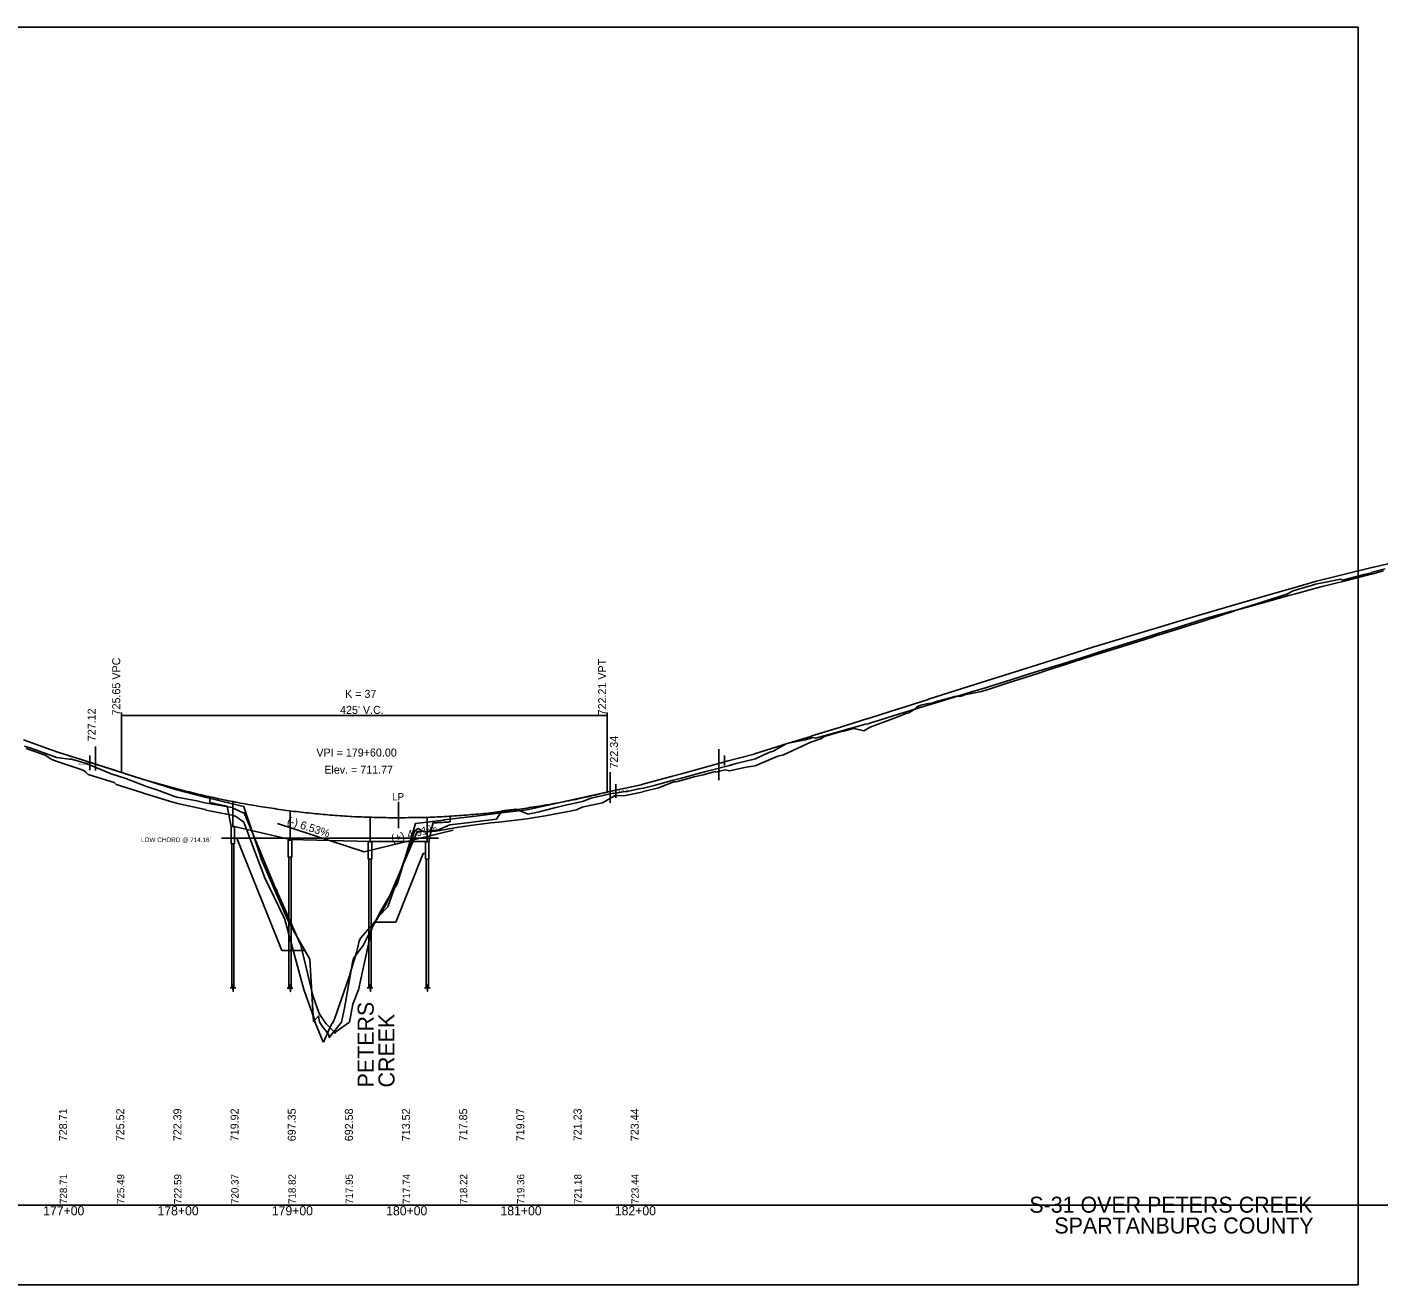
# Model space of a CAD drawing. Extents: x 1741783 to 1745041, y 1152835 to 1153935.
# Drawn here: x 1743218 to 1744400, y 1152835 to 1153935 of the extents above; entities that cross this region are included whole.
import ezdxf

# ---------------------------------------------------------------- set-up
doc = ezdxf.new("R2010")
doc.units = 0
for name, color, linetype in [('BR_CONCRETE', 7, 'Continuous'), ('BR_EXIST_GROUND_LT', 7, 'Continuous'), ('BR_EXIST_GROUND_RT', 7, 'Continuous'), ('BR_USER NOTES', 7, 'Continuous'), ('GN_Clip', 7, 'Continuous'), ('RD_DDB_GradeTX', 7, 'Continuous'), ('RD_DDB_Profile_EX', 7, 'Continuous'), ('RD_DDB_Profile_Lbl', 7, 'Continuous'), ('RD_DDB_Profile_PR', 7, 'Continuous'), ('RD_DDB_StaTX', 7, 'Continuous'), ('RD_DDB_StripGrade', 7, 'Continuous'), ('RD_DDB_VCLbl', 7, 'Continuous'), ('RD_GPK_Profile_Cell', 7, 'Continuous'), ('RD_SHT_TX', 7, 'Continuous')]:
    doc.layers.add(name, color=color, linetype=linetype)

msp = doc.modelspace()

# ---------------------------------------------------------------- linework, layer by layer
at = {"layer": 'BR_CONCRETE'}
for p, q in [((1743377.7, 1153257.2), (1743377.7, 1153262.3)), ((1743396.2, 1153236.2), (1743392.7, 1153254)), ((1743397.7, 1153236.6), (1743397.7, 1153258.1)), ((1743447.7, 1153224.9), (1743447.7, 1153250)), ((1743517.7, 1153223), (1743517.7, 1153244.3)), ((1743567.7, 1153223.2), (1743567.7, 1153244.4)), ((1743587.7, 1153240.3), (1743587.7, 1153245.3)), ((1743397.7, 1153236.6), (1743397.7, 1153236.2)), ((1743397.7, 1153236.6), (1743447.7, 1153224.9)), ((1743569.2, 1153222.8), (1743572.6, 1153239.5)), ((1743396.7, 1153095.1), (1743396.7, 1153221.2)), ((1743398.7, 1153095.1), (1743398.7, 1153221.2)), ((1743399.2, 1153226), (1743401.2, 1153226)), ((1743401.2, 1153226), (1743440.5, 1153127.8)), ((1743447.7, 1153224.9), (1743447.7, 1153224.4)), ((1743517.7, 1153223.2), (1743447.7, 1153224.9)), ((1743517.7, 1153223.2), (1743517.7, 1153222.8)), ((1743517.7, 1153223.2), (1743567.7, 1153223.2)), ((1743567.7, 1153223.2), (1743567.7, 1153222.8)), ((1743446.7, 1153094.9), (1743446.7, 1153209.4)), ((1743446.7, 1153209.4), (1743448.7, 1153209.4)), ((1743448.7, 1153094.9), (1743448.7, 1153209.4)), ((1743516.7, 1153095.1), (1743516.7, 1153207.8)), ((1743516.7, 1153207.8), (1743518.7, 1153207.8)), ((1743518.7, 1153095.1), (1743518.7, 1153207.8)), ((1743564.2, 1153212.8), (1743540.2, 1153152.8)), ((1743566.2, 1153212.8), (1743564.2, 1153212.8)), ((1743566.7, 1153095.1), (1743566.7, 1153207.8)), ((1743568.7, 1153095.1), (1743568.7, 1153207.8)), ((1743522.2, 1153152.8), (1743540.2, 1153152.8)), ((1743440.5, 1153127.8), (1743460.8, 1153127.8))]:
    msp.add_line(p, q, dxfattribs=at)
for points in [[(1743396.2, 1153236.2), (1743399.2, 1153236.2), (1743399.2, 1153221.2), (1743396.2, 1153221.2)], [(1743446.2, 1153224.4), (1743449.2, 1153224.4), (1743449.2, 1153209.4), (1743446.2, 1153209.4)], [(1743516.2, 1153222.8), (1743519.2, 1153222.8), (1743519.2, 1153207.8), (1743516.2, 1153207.8)], [(1743569.2, 1153222.8), (1743566.2, 1153222.8), (1743566.2, 1153207.8), (1743569.2, 1153207.8)]]:
    msp.add_lwpolyline(points, close=True, dxfattribs=at)
for points in [[(1743400.2, 1153095.1), (1743398, 1153095.1), (1743398, 1153092.1), (1743397.4, 1153098.1), (1743397.4, 1153095.1), (1743395.3, 1153095.1)], [(1743450.2, 1153094.9), (1743448, 1153094.9), (1743448, 1153091.9), (1743447.4, 1153097.9), (1743447.4, 1153094.9), (1743445.3, 1153094.9)], [(1743520.2, 1153095.1), (1743518, 1153095.1), (1743518, 1153092.1), (1743517.4, 1153098.1), (1743517.4, 1153095.1), (1743515.3, 1153095.1)], [(1743570.2, 1153095.1), (1743568, 1153095.1), (1743568, 1153092.1), (1743567.4, 1153098.1), (1743567.4, 1153095.1), (1743565.3, 1153095.1)]]:
    msp.add_lwpolyline(points, dxfattribs=at)
for points in [[(1743377.7, 1153257.2), (1743379.7, 1153256.7), (1743381.7, 1153256.3), (1743384.8, 1153255.6), (1743385.9, 1153255.4), (1743388.1, 1153254.9), (1743389.2, 1153254.7), (1743391.1, 1153254.3), (1743391.9, 1153254.2), (1743392.7, 1153254)], [(1743572.6, 1153239.5), (1743574.7, 1153239.6), (1743576.9, 1153239.7), (1743581.3, 1153239.9), (1743583.6, 1153240.1), (1743586.5, 1153240.2), (1743587.1, 1153240.3), (1743587.7, 1153240.3)]]:
    msp.add_open_spline(points, degree=3, dxfattribs=at)
at = {"layer": 'BR_EXIST_GROUND_LT'}
msp.add_lwpolyline([(1743215.6, 1153306.5), (1743220.9, 1153304.7), (1743240.5, 1153297.7), (1743241.2, 1153297.5), (1743243.5, 1153296.7), (1743254.7, 1153295.2), (1743256.5, 1153295.1), (1743269.7, 1153291.3), (1743291.4, 1153282.3), (1743297.8, 1153280.3), (1743304.2, 1153278.2), (1743322.1, 1153271.3), (1743331.2, 1153268.5), (1743346.2, 1153262.8), (1743348.7, 1153262), (1743366.1, 1153258.7), (1743373.2, 1153256.9), (1743397, 1153252.8), (1743397.5, 1153252.5), (1743406.8, 1153248.4), (1743407.7, 1153248.2), (1743435.3, 1153181.6), (1743435.5, 1153181.9), (1743436.5, 1153179.3), (1743457.2, 1153132.5), (1743467.8, 1153088.6), (1743473.2, 1153072.7), (1743477.8, 1153065.7), (1743479.4, 1153063.9), (1743486.9, 1153056.1), (1743487, 1153055.5), (1743488.2, 1153057), (1743499.7, 1153065.3), (1743502.7, 1153081), (1743507.7, 1153093.4), (1743520, 1153149.4), (1743523.3, 1153155), (1743525, 1153157.7), (1743533.3, 1153166.1), (1743555.7, 1153229.5), (1743556.7, 1153231.3), (1743557.6, 1153233.1), (1743559.7, 1153234.7), (1743565, 1153231.6), (1743576.6, 1153233), (1743587.5, 1153237.7), (1743602.7, 1153239.4), (1743611.8, 1153240.8), (1743628.2, 1153242.7), (1743633, 1153250), (1743645.2, 1153251.4), (1743656.1, 1153247.2), (1743665.5, 1153249.1), (1743679.1, 1153252.6), (1743680.5, 1153252.9), (1743688.7, 1153255), (1743703.5, 1153258.3), (1743711.1, 1153261.1), (1743730.5, 1153265.5), (1743731, 1153265.3), (1743739.2, 1153266.5), (1743742.7, 1153266.9), (1743752.8, 1153269.4), (1743757, 1153269.8), (1743766.2, 1153272.3), (1743782, 1153276.5), (1743789.1, 1153278.4), (1743807.1, 1153283.2), (1743811.5, 1153284.4), (1743832.1, 1153289.8), (1743833, 1153290), (1743838, 1153291.3), (1743854.9, 1153295.5), (1743856.6, 1153296.4), (1743861.7, 1153298.7), (1743867.4, 1153301.2), (1743870.2, 1153302.1), (1743881.6, 1153308.7), (1743882.1, 1153308.8), (1743898.5, 1153312.1), (1743903.2, 1153313.6), (1743904.9, 1153314.1), (1743907.5, 1153313.6), (1743927.4, 1153319.1), (1743931.2, 1153320.3), (1743951, 1153325.7), (1743953.5, 1153326.2), (1743954.8, 1153326.7), (1743955.8, 1153326.9), (1743957.9, 1153327.5), (1743980.8, 1153334.7), (1743985.7, 1153336.2), (1744005.7, 1153342.4), (1744012.7, 1153344.5), (1744030.7, 1153350), (1744043.9, 1153354.1), (1744053.1, 1153356.8), (1744068.8, 1153361.7), (1744078.1, 1153364.6), (1744094.6, 1153369.7), (1744103, 1153372.4), (1744120.5, 1153377.8), (1744128, 1153380.1), (1744145.6, 1153385.6), (1744151.7, 1153387.5), (1744157.8, 1153389.5), (1744176.6, 1153395.4), (1744182.3, 1153397.3), (1744201.6, 1153403.4), (1744206.7, 1153405.1), (1744226.5, 1153411.3), (1744230.1, 1153412.5), (1744246.6, 1153417.7), (1744251.3, 1153419), (1744271.5, 1153424.6), (1744276.6, 1153425.9), (1744296.5, 1153431.4), (1744301.9, 1153432.8), (1744321.4, 1153438.3), (1744327.3, 1153439.8), (1744345, 1153444.7), (1744350.6, 1153446.2), (1744369.9, 1153451), (1744377.7, 1153453), (1744394.9, 1153457.3), (1744404.3, 1153459.8)], dxfattribs=at)
at = {"layer": 'BR_EXIST_GROUND_RT'}
msp.add_lwpolyline([(1743216.9, 1153304.6), (1743233.6, 1153298.6), (1743239.5, 1153294.9), (1743244, 1153293.3), (1743265.8, 1153286), (1743267.6, 1153285.1), (1743269, 1153283.9), (1743271.2, 1153281.9), (1743293.9, 1153274.7), (1743295.7, 1153273.1), (1743318.9, 1153265.9), (1743319.5, 1153265.6), (1743343.2, 1153258.3), (1743344.3, 1153257.8), (1743349.3, 1153256.3), (1743373.5, 1153251.3), (1743374.2, 1153250.7), (1743398.7, 1153245.8), (1743399.1, 1153245.5), (1743399.9, 1153245.4), (1743407.3, 1153240), (1743418.8, 1153209.7), (1743424.7, 1153193.7), (1743425.3, 1153191.9), (1743441.9, 1153157.5), (1743443.2, 1153155.1), (1743459.9, 1153093.8), (1743468.8, 1153068.5), (1743469.3, 1153065.4), (1743476.5, 1153048.6), (1743477, 1153047.8), (1743483.8, 1153062.9), (1743485.5, 1153065.2), (1743487, 1153068.8), (1743499.6, 1153105.8), (1743500.4, 1153108), (1743505.9, 1153126), (1743506.6, 1153129.5), (1743508.1, 1153136.1), (1743509.3, 1153138.6), (1743523.6, 1153155.1), (1743531.7, 1153168.5), (1743558.5, 1153231.2), (1743559.2, 1153231.9), (1743560.5, 1153232.1), (1743569.1, 1153231.7), (1743577.1, 1153232.6), (1743595.3, 1153235.8), (1743601.4, 1153236.5), (1743605.3, 1153237.2), (1743623.5, 1153239.4), (1743630.5, 1153240.1), (1743647.5, 1153242.2), (1743655, 1153243), (1743672.5, 1153245.9), (1743679.9, 1153247.5), (1743691.3, 1153249.4), (1743698.4, 1153250.9), (1743703.4, 1153253.3), (1743720.9, 1153257), (1743731.6, 1153263), (1743741.2, 1153263.4), (1743755.4, 1153266.4), (1743755.8, 1153266.5), (1743770.1, 1153270.1), (1743783.5, 1153275.4), (1743784.9, 1153275.4), (1743786.6, 1153275.8), (1743801.2, 1153279.8), (1743809, 1153281.6), (1743819.5, 1153284.5), (1743820.2, 1153283.8), (1743828.3, 1153285.8), (1743832.2, 1153285.1), (1743846.8, 1153288.2), (1743854.5, 1153289.3), (1743874.3, 1153297.8), (1743879.3, 1153299.1), (1743903.8, 1153310.3), (1743904.1, 1153310.4), (1743912.7, 1153313.3), (1743914.9, 1153314.9), (1743928.9, 1153319.2), (1743932.1, 1153319.7), (1743933.1, 1153320.1), (1743937.5, 1153321.2), (1743941.3, 1153321.9), (1743949.7, 1153320.1), (1743955.3, 1153323.2), (1743979.4, 1153332.3), (1743980, 1153332.6), (1743986.8, 1153335), (1743989.1, 1153335.7), (1743993.7, 1153338.7), (1743996.1, 1153341), (1743999.6, 1153342.4), (1744004.5, 1153343.6), (1744009, 1153344.2), (1744014, 1153345.8), (1744014.4, 1153345.9), (1744030.3, 1153350.2), (1744033.7, 1153349.9), (1744036.4, 1153351), (1744037.6, 1153351.5), (1744052.7, 1153354.3), (1744060, 1153356.7), (1744077.7, 1153362.4), (1744084.3, 1153364.6), (1744102.7, 1153370.5), (1744108.5, 1153372.5), (1744127.7, 1153378.6), (1744132.2, 1153380.1), (1744151.1, 1153386.1), (1744153.9, 1153387), (1744176, 1153393.8), (1744179.6, 1153395), (1744200.9, 1153401.6), (1744205.1, 1153403), (1744225.9, 1153409.4), (1744230.4, 1153411), (1744248.2, 1153416.5), (1744272.3, 1153424.4), (1744272.9, 1153424.6), (1744275.4, 1153425.4), (1744297.7, 1153432.6), (1744300.3, 1153433.3), (1744319.5, 1153439.5), (1744325.2, 1153442.3), (1744333.9, 1153444.9), (1744341.1, 1153447.2), (1744344.7, 1153448.3), (1744355.2, 1153450.3), (1744366.7, 1153452.6), (1744368.4, 1153451.8), (1744387.3, 1153456.6), (1744391.1, 1153457.5), (1744393.7, 1153458.2), (1744394.2, 1153458.8), (1744405.7, 1153461.7)], dxfattribs=at)
at = {"layer": 'BR_USER NOTES'}
for p, q in [((1743277.7, 1153306.3), (1743277.7, 1153285.3)), ((1743822.7, 1153303.9), (1743822.7, 1153276.7)), ((1743272.7, 1153298.3), (1743272.7, 1153285.6)), ((1743272.7, 1153292.5), (1743277.7, 1153290.9)), ((1743822.7, 1153291.4), (1743827.7, 1153292.7)), ((1743827.7, 1153298.3), (1743827.7, 1153289.8)), ((1743727.7, 1153283.8), (1743727.7, 1153257)), ((1743727.7, 1153267), (1743732.7, 1153268.1)), ((1743732.7, 1153273.4), (1743732.7, 1153261.5)), ((1743542.7, 1153258), (1743542.7, 1153234.8)), ((1743542.7, 1153258), (1743542.7, 1153234.8)), ((1743447.7, 1153226.1), (1743447.7, 1153247.2)), ((1743387.7, 1153226.1), (1743577.7, 1153226.1))]:
    msp.add_line(p, q, dxfattribs=at)
at = {"layer": 'GN_Clip'}
for p, q in [((1742582, 1153935.4), (1744382, 1153935.4)), ((1744382, 1153935.4), (1744382, 1152835.4)), ((1744382, 1152835.4), (1742582, 1152835.4))]:
    msp.add_line(p, q, dxfattribs=at)
at = {"layer": 'RD_DDB_GradeTX'}
for p in [(1743436.7, 1153239), (1743590.4, 1153233.2)]:
    msp.add_line(p, (1743512.7, 1153214.2), dxfattribs=at)
at = {"layer": 'RD_DDB_Profile_EX'}
msp.add_lwpolyline([(1743214.7, 1153312), (1743238.8, 1153303.5), (1743239.7, 1153303.2), (1743244.7, 1153301.4), (1743245.6, 1153301.1), (1743269.7, 1153293.4), (1743270.4, 1153293.2), (1743294.6, 1153285.5), (1743295.2, 1153285.3), (1743319.6, 1153277.5), (1743319.9, 1153277.4), (1743344.5, 1153269.6), (1743348.6, 1153268.3), (1743373.5, 1153262.1), (1743398.5, 1153255.9), (1743407.4, 1153253.7), (1743408, 1153251.9), (1743421.2, 1153212), (1743422.4, 1153208), (1743445.1, 1153155.9), (1743445.5, 1153154.9), (1743447, 1153152.2), (1743465, 1153120.2), (1743468.3, 1153065.9), (1743472.7, 1153070.6), (1743473.5, 1153065.5), (1743475.9, 1153061.6), (1743481.4, 1153054.8), (1743482, 1153051.7), (1743492.6, 1153065.2), (1743495.3, 1153077.4), (1743502.5, 1153117.3), (1743503.4, 1153121.6), (1743511.7, 1153132.4), (1743515.5, 1153139.9), (1743527.2, 1153162.7), (1743533.1, 1153172.5), (1743541.7, 1153186.6), (1743542.4, 1153188.7), (1743549.3, 1153211.7), (1743557.6, 1153239), (1743581.9, 1153242), (1743582.6, 1153242.1), (1743607.1, 1153245.1), (1743607.6, 1153245.1), (1743632.6, 1153248.2), (1743654.9, 1153250.9), (1743679.9, 1153256.4), (1743704.9, 1153261.9), (1743729.8, 1153267.4), (1743754.8, 1153272.9), (1743756.3, 1153273.3), (1743781, 1153280), (1743790, 1153282.5), (1743806, 1153286.8), (1743831, 1153293.6), (1743853.6, 1153299.7), (1743853.9, 1153299.8), (1743878.3, 1153307.4), (1743878.9, 1153307.6), (1743903.2, 1153315.1), (1743904.2, 1153315.5), (1743928.3, 1153322.9), (1743929.2, 1153323.2), (1743953.1, 1153330.7), (1743953.8, 1153330.9), (1743955.1, 1153331.3), (1743956.2, 1153331.6), (1743980.1, 1153339.3), (1743981.1, 1153339.6), (1744005, 1153347.2), (1744006.1, 1153347.6), (1744030, 1153355.2), (1744051.5, 1153362), (1744052.4, 1153362.3), (1744076.4, 1153369.9), (1744077.4, 1153370.2), (1744101.4, 1153377.8), (1744102.3, 1153378.1), (1744126.4, 1153385.7), (1744127.3, 1153386), (1744150.7, 1153393.4), (1744151.4, 1153393.6), (1744152.1, 1153393.8), (1744176.3, 1153401.1), (1744177.2, 1153401.4), (1744201.3, 1153408.6), (1744202.3, 1153408.9), (1744226.2, 1153416.1), (1744245.8, 1153422), (1744246.9, 1153422.3), (1744270.9, 1153429.2), (1744271.9, 1153429.5), (1744296.1, 1153436.5), (1744296.8, 1153436.8), (1744321.3, 1153443.8), (1744321.8, 1153444), (1744345.7, 1153450.9), (1744363.3, 1153455.2), (1744370.5, 1153457), (1744395.2, 1153463), (1744395.7, 1153463.1), (1744420.1, 1153469)], dxfattribs=at)
at = {"layer": 'RD_DDB_Profile_PR'}
for p, q in [((1743277.7, 1153290.9), (1743300.2, 1153283.5)), ((1743725.2, 1153266.4), (1743727.7, 1153267))]:
    msp.add_line(p, q, dxfattribs=at)
msp.add_spline([(1743300.2, 1153283.5), (1743308.7, 1153280.8), (1743317.2, 1153278.2), (1743325.7, 1153275.6), (1743334.2, 1153273.2), (1743342.7, 1153270.9), (1743351.2, 1153268.6), (1743359.7, 1153266.5), (1743368.2, 1153264.4), (1743376.7, 1153262.5), (1743385.2, 1153260.6), (1743393.7, 1153258.9), (1743402.2, 1153257.2), (1743410.7, 1153255.7), (1743419.2, 1153254.2), (1743427.7, 1153252.9), (1743436.2, 1153251.6), (1743444.7, 1153250.4), (1743453.2, 1153249.3), (1743461.7, 1153248.4), (1743470.2, 1153247.5), (1743478.7, 1153246.7), (1743487.2, 1153246), (1743495.7, 1153245.4), (1743504.2, 1153244.9), (1743512.7, 1153244.6), (1743521.2, 1153244.3), (1743529.7, 1153244.1), (1743538.2, 1153244), (1743546.7, 1153244), (1743555.2, 1153244.1), (1743563.7, 1153244.2), (1743572.2, 1153244.5), (1743580.7, 1153244.9), (1743589.2, 1153245.4), (1743597.7, 1153246), (1743606.2, 1153246.7), (1743614.7, 1153247.4), (1743623.2, 1153248.3), (1743631.7, 1153249.3), (1743640.2, 1153250.3), (1743648.7, 1153251.5), (1743657.2, 1153252.8), (1743665.7, 1153254.1), (1743674.2, 1153255.6), (1743682.7, 1153257.1), (1743691.2, 1153258.8), (1743699.7, 1153260.5), (1743708.2, 1153262.4), (1743716.7, 1153264.3), (1743725.2, 1153266.4)], degree=3, dxfattribs=at)
at = {"layer": 'RD_DDB_VCLbl'}
for p, q in [((1743300.2, 1153336), (1743300.2, 1153283.5)), ((1743725.2, 1153336), (1743725.2, 1153266.4)), ((1743300.2, 1153333.5), (1743725.2, 1153333.5))]:
    msp.add_line(p, q, dxfattribs=at)
at = {"layer": 'RD_GPK_Profile_Cell'}
msp.add_line((1741866.9, 1152905.3), (1745041.2, 1152905.3), dxfattribs=at)

# ---------------------------------------------------------------- texts
at = {"layer": 'BR_USER NOTES'}
for s, height, p in [('-6.3800', 2, (1743262.2, 1153290.1)), ('LP', 6.4, (1743537, 1153259.1)), ('LP', 6.4, (1743537, 1153259.1)), ('+4.4120', 2, (1743733.5, 1153266.4)), ("LOW CHORD @ 714.16'", 4, (1743317.4, 1153222.7))]:
    msp.add_text(s, height=height, dxfattribs=at).set_placement(p)
at = {"layer": 'RD_DDB_GradeTX'}
for s, rotation, p in [('(-) 6.53%', 341.9218, (1743444.6, 1153238.5)), ('(+) 4.91%', 13.7987, (1743537.2, 1153222.2))]:
    msp.add_text(s, height=7, rotation=rotation, dxfattribs=at).set_placement(p)
at = {"layer": 'RD_DDB_Profile_Lbl'}
for s, p in [('727.12', (1743277.7, 1153310.9)), ('722.34', (1743734.5, 1153287))]:
    msp.add_text(s, height=7, rotation=90, dxfattribs=at).set_placement(p)
for s, p in [('VPI = 179+60.00', (1743470.8, 1153297.5)), ('Elev. = 711.77', (1743477.7, 1153282.5))]:
    msp.add_text(s, height=7, dxfattribs=at).set_placement(p)
at = {"layer": 'RD_DDB_StaTX'}
for s, p in [('177+00', (1743231.8, 1152896.3)), ('178+00', (1743331.8, 1152896.3)), ('179+00', (1743431.8, 1152896.3)), ('180+00', (1743531.8, 1152896.3)), ('181+00', (1743631.8, 1152896.3)), ('182+00', (1743731.8, 1152896.3))]:
    msp.add_text(s, height=8, dxfattribs=at).set_placement(p)
at = {"layer": 'RD_DDB_StripGrade'}
for s, height, p in [('725.65 VPC', 7, (1743299.2, 1153333.5)), ('722.21 VPT', 7, (1743724.2, 1153333.5)), ('728.71', 7, (1743252.7, 1152961.1)), ('725.52', 7, (1743302.7, 1152961.1)), ('722.39', 7, (1743352.7, 1152961.1)), ('719.92', 7, (1743402.7, 1152961.1)), ('697.35', 7, (1743452.7, 1152961.1)), ('692.58', 7, (1743502.7, 1152961.1)), ('713.52', 7, (1743552.7, 1152961.1)), ('717.85', 7, (1743602.7, 1152961.1)), ('719.07', 7, (1743652.7, 1152961.1)), ('721.23', 7, (1743702.7, 1152961.1)), ('723.44', 7, (1743752.7, 1152961.1)), ('728.71', 6.4, (1743252.7, 1152906.2)), ('725.49', 6.4, (1743302.7, 1152906.2)), ('722.59', 6.4, (1743352.7, 1152906.2)), ('720.37', 6.4, (1743402.7, 1152906.2)), ('718.82', 6.4, (1743452.7, 1152906.2)), ('717.95', 6.4, (1743502.7, 1152906.2)), ('717.74', 6.4, (1743552.7, 1152906.2)), ('718.22', 6.4, (1743602.7, 1152906.2)), ('719.36', 6.4, (1743652.7, 1152906.2)), ('721.18', 6.4, (1743702.7, 1152906.2)), ('723.44', 6.4, (1743752.7, 1152906.2))]:
    msp.add_text(s, height=height, rotation=90, dxfattribs=at).set_placement(p)
at = {"layer": 'RD_DDB_VCLbl'}
for s, p in [('K = 37', (1743495.9, 1153348.8)), ("425' V.C.", (1743491.5, 1153334.8))]:
    msp.add_text(s, height=7, dxfattribs=at).set_placement(p)
at = {"layer": 'RD_SHT_TX'}
for s, rotation, p in [('PETERS ', 90, (1743520.9, 1153008.1)), ('CREEK', 90, (1743539.1, 1153008.1)), ('S-31 OVER PETERS CREEK', 360, (1744094.4, 1152898.6)), ('SPARTANBURG COUNTY', 360, (1744116.3, 1152880.4))]:
    msp.add_text(s, height=14, rotation=rotation, dxfattribs=at).set_placement(p)

doc.saveas('drawing.dxf')
